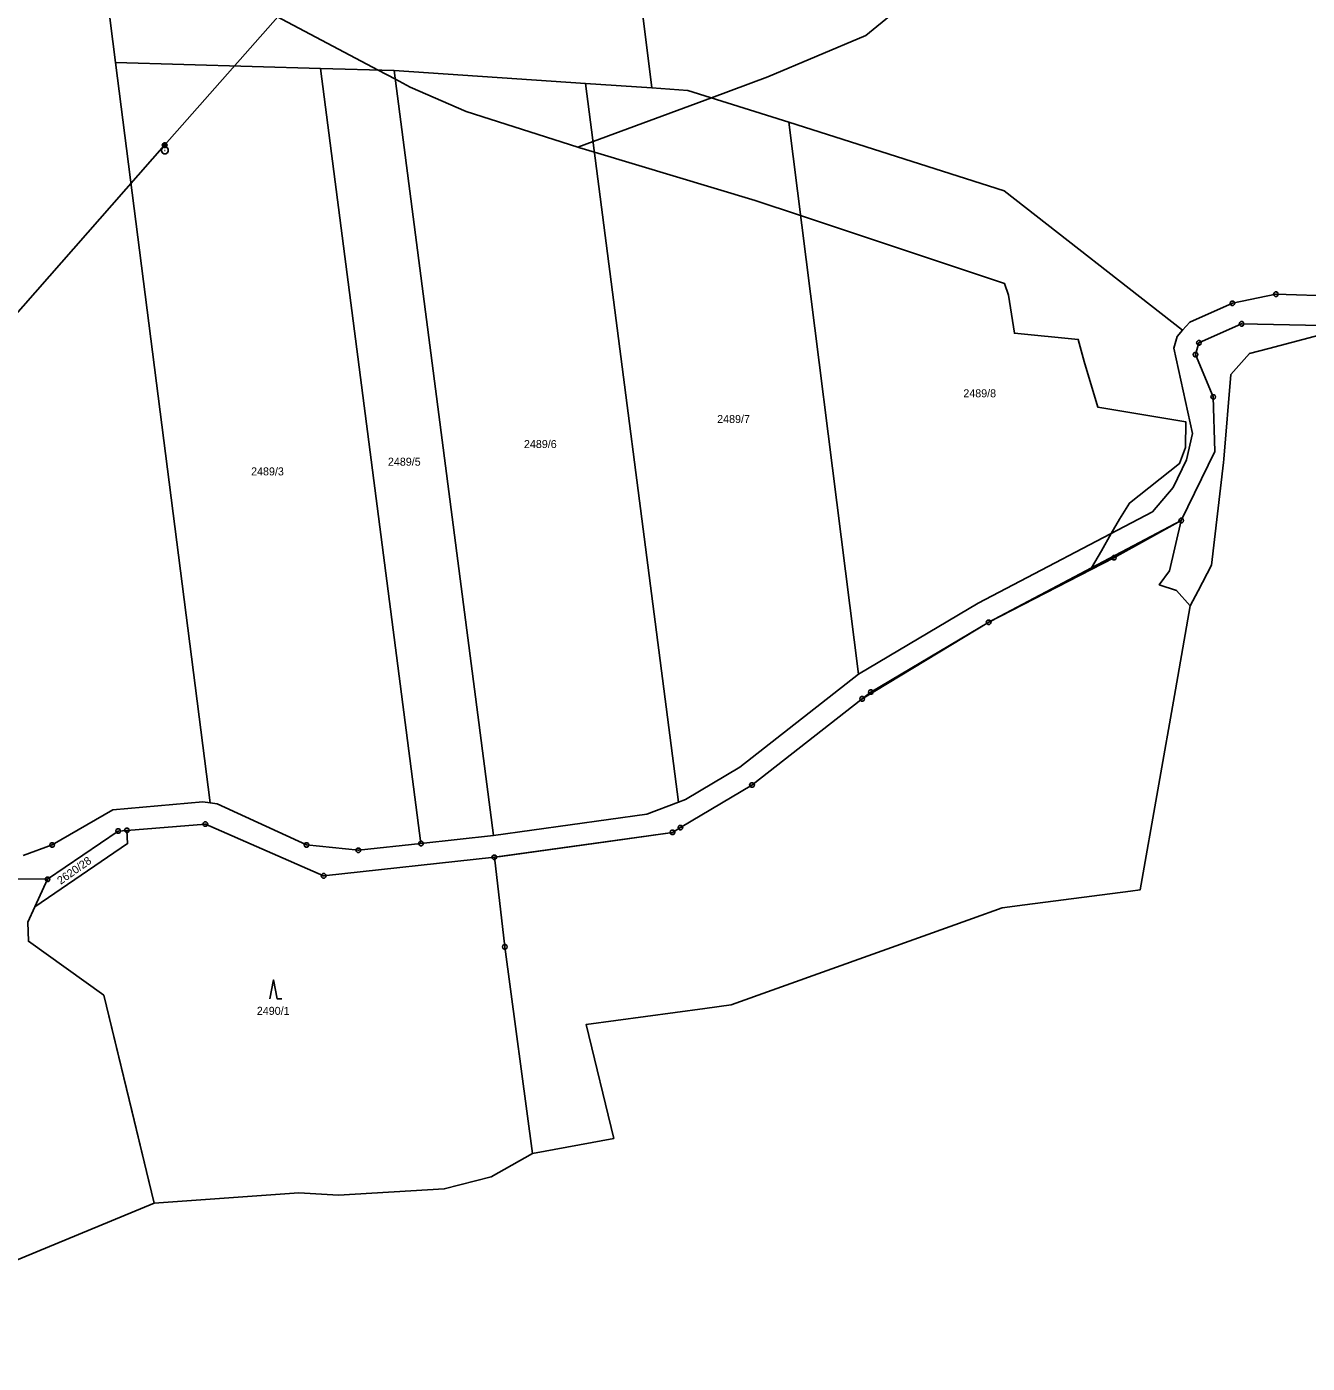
# Model space of a CAD drawing. Extents: x -760611 to -758411, y -1176479 to -1174807.
# Drawn here: x -759249.4 to -758977.4, y -1175576.9 to -1175293 of the extents above; entities that cross this region are included whole.
import ezdxf

# ---------------------------------------------------------------- set-up
doc = ezdxf.new("R2010")
doc.units = 0
for name, color, linetype in [('1', 7, 'Continuous'), ('11', 7, 'Continuous'), ('2', 7, 'Continuous'), ('3', 7, 'Continuous'), ('6', 7, 'Continuous'), ('8', 7, 'Continuous')]:
    doc.layers.add(name, color=color, linetype=linetype)

msp = doc.modelspace()

# ---------------------------------------------------------------- linework, layer by layer
at = {"layer": '1'}
for p, q in [((-759239.1, -1175233.43), (-759230.51, -1175300.62)), ((-759124.57, -1175242.76), (-759116.61, -1175306.03)), ((-759230.51, -1175300.62), (-759210.41, -1175457.91)), ((-759186.97, -1175301.88), (-759230.51, -1175300.62)), ((-759171.32, -1175302.34), (-759186.97, -1175301.88)), ((-759186.97, -1175301.88), (-759165.64, -1175466.52)), ((-759171.32, -1175302.34), (-759150.26, -1175464.85)), ((-759130.69, -1175305.08), (-759171.32, -1175302.34)), ((-759130.69, -1175305.08), (-759116.61, -1175306.03)), ((-759110.92, -1175457.7), (-759130.69, -1175305.08)), ((-759116.61, -1175306.03), (-759108.97, -1175306.54)), ((-759108.97, -1175306.54), (-759087.54, -1175313.33)), ((-759041.78, -1175327.91), (-759087.54, -1175313.33)), ((-759087.54, -1175313.33), (-759072.7, -1175430.56)), ((-759003.87, -1175357.51), (-759041.78, -1175327.91)), ((-758993.3, -1175351.77), (-759002.36, -1175355.79)), ((-758984.06, -1175349.84), (-758993.3, -1175351.77)), ((-758969.35, -1175350.34), (-758984.06, -1175349.84)), ((-759005.01, -1175358.82), (-759003.87, -1175357.51)), ((-759003.87, -1175357.51), (-759002.36, -1175355.79)), ((-759000.41, -1175360.18), (-758991.35, -1175356.15)), ((-758991.35, -1175356.15), (-758967.69, -1175356.63)), ((-759005.01, -1175358.82), (-759005.75, -1175361.32)), ((-759001.15, -1175362.68), (-759000.41, -1175360.18)), ((-759005.75, -1175361.32), (-759001.76, -1175379.4)), ((-758997.36, -1175371.67), (-759001.15, -1175362.68)), ((-758997.06, -1175383.23), (-758997.36, -1175371.67)), ((-759001.76, -1175379.4), (-759003.02, -1175385)), ((-759004.16, -1175397.91), (-758997.06, -1175383.23)), ((-759003.02, -1175385), (-759005.87, -1175390.89)), ((-759005.87, -1175390.89), (-759010.3, -1175396.05)), ((-759010.3, -1175396.05), (-759047.29, -1175415.5)), ((-759018.46, -1175405.83), (-759004.16, -1175397.91)), ((-759045.06, -1175419.53), (-759018.46, -1175405.83)), ((-759047.29, -1175415.5), (-759072.7, -1175430.56)), ((-759070.1, -1175434.37), (-759045.06, -1175419.53)), ((-759097.94, -1175450.29), (-759072.7, -1175430.56)), ((-759071.93, -1175435.8), (-759095.34, -1175454.1)), ((-759070.1, -1175434.37), (-759071.93, -1175435.8)), ((-759097.94, -1175450.29), (-759109.43, -1175457.14)), ((-759095.34, -1175454.1), (-759110.54, -1175463.15)), ((-759231.12, -1175459.35), (-759243.97, -1175466.82)), ((-759211.95, -1175457.67), (-759231.12, -1175459.35)), ((-759211.95, -1175457.67), (-759210.41, -1175457.91)), ((-759210.41, -1175457.91), (-759208.95, -1175458.12)), ((-759189.96, -1175466.83), (-759208.95, -1175458.12)), ((-759117.67, -1175460.27), (-759110.92, -1175457.7)), ((-759110.92, -1175457.7), (-759109.43, -1175457.14)), ((-759211.43, -1175462.39), (-759228.09, -1175463.72)), ((-759211.43, -1175462.39), (-759186.31, -1175473.39)), ((-759117.67, -1175460.27), (-759150.26, -1175464.85)), ((-759244.94, -1175474.11), (-759229.95, -1175463.87)), ((-759228.09, -1175463.72), (-759229.95, -1175463.87)), ((-759227.96, -1175466.53), (-759228.09, -1175463.72)), ((-759165.64, -1175466.52), (-759150.26, -1175464.85)), ((-759150.05, -1175469.45), (-759112.22, -1175464.15)), ((-759110.54, -1175463.15), (-759112.22, -1175464.15)), ((-759243.97, -1175466.82), (-759250.12, -1175469.05)), ((-759247.64, -1175479.98), (-759227.96, -1175466.53)), ((-759178.94, -1175467.96), (-759189.96, -1175466.83)), ((-759178.94, -1175467.96), (-759165.64, -1175466.52)), ((-759150.05, -1175469.45), (-759186.31, -1175473.39)), ((-759150.05, -1175469.45), (-759147.83, -1175488.47)), ((-759274.94, -1175473.79), (-759244.94, -1175474.11)), ((-759244.94, -1175474.11), (-759247.64, -1175479.98)), ((-759247.64, -1175479.98), (-759249.13, -1175483.21)), ((-759249.01, -1175487.28), (-759249.13, -1175483.21)), ((-759233.01, -1175498.74), (-759249.01, -1175487.28)), ((-759147.83, -1175488.47), (-759141.95, -1175532.33)), ((-759222.29, -1175542.91), (-759233.01, -1175498.74)), ((-759141.95, -1175532.33), (-759150.72, -1175537.34)), ((-759150.72, -1175537.34), (-759160.7, -1175539.89)), ((-759191.58, -1175540.71), (-759222.29, -1175542.91)), ((-759183.19, -1175541.19), (-759191.58, -1175540.71)), ((-759160.7, -1175539.89), (-759183.19, -1175541.19))]:
    msp.add_line(p, q, dxfattribs=at)
at = {"layer": '11'}
msp.add_line((-759002.27, -1175416.06), (-759005.42, -1175433.87), dxfattribs=at)
for points in [[(-758975.79, -1175178.19), (-758988.73, -1175187.68), (-758988.97, -1175187.85), (-758998.77, -1175199.65), (-759009, -1175216.53), (-759019.77, -1175236.09), (-759024.8, -1175245.22), (-759039.29, -1175265.46), (-759053.76, -1175280.62), (-759071.19, -1175294.92), (-759092, -1175303.7), (-759103.96, -1175308.13), (-759129.09, -1175317.42), (-759132.3, -1175318.61)], [(-759132.3, -1175318.61), (-759156.06, -1175311), (-759167.91, -1175305.86), (-759171.08, -1175304.18), (-759174.75, -1175302.24), (-759227.58, -1175274.25), (-759234.21, -1175271.67), (-759244.09, -1175267.82), (-759256.38, -1175263.95), (-759258.05, -1175258.44), (-759258.03, -1175252.52), (-759275.43, -1175254.97), (-759297.92, -1175261.21), (-759298.65, -1175261.35), (-759302.17, -1175262.03)], [(-759132.3, -1175318.61), (-759131.91, -1175318.74), (-759128.8, -1175319.67), (-759094.64, -1175329.93), (-759085.04, -1175333.12), (-759041.7, -1175347.54), (-759040.86, -1175350.08), (-759039.62, -1175358.13), (-759026.06, -1175359.46), (-759024.8, -1175364.13), (-759021.87, -1175373.87), (-759003.22, -1175376.93), (-759003.24, -1175382.43), (-759004.53, -1175385.81), (-759015.16, -1175394.22), (-759017.29, -1175397.59), (-759019.02, -1175400.64), (-759021.13, -1175404.34), (-759023.2, -1175407.97)], [(-758993.67, -1175366.93), (-758989.69, -1175362.44), (-758985.6, -1175361.36), (-758967.69, -1175356.63), (-758957.61, -1175355.92), (-758936.92, -1175355.2), (-758892.8, -1175353.02)], [(-758993.67, -1175366.93), (-758995.11, -1175384.9), (-758995.19, -1175385.57), (-758997.73, -1175407.38), (-759000.61, -1175412.88), (-759002.27, -1175416.06)], [(-759023.2, -1175407.97), (-759004.16, -1175397.91), (-759006.64, -1175408.62), (-759008.83, -1175411.55), (-759005.17, -1175412.8), (-759002.27, -1175416.06)], [(-759095.34, -1175454.1), (-759071.93, -1175435.8), (-759045.06, -1175419.53), (-759023.2, -1175407.97)], [(-759005.42, -1175433.87), (-759012.92, -1175476.36), (-759014.96, -1175476.62), (-759037.4, -1175479.54), (-759042.19, -1175480.16), (-759048.51, -1175482.42), (-759058.95, -1175486.17), (-759099.79, -1175500.8), (-759105.33, -1175501.55), (-759130.53, -1175504.94), (-759124.69, -1175529.2)], [(-759222.29, -1175542.91), (-759223.5, -1175537.94), (-759227, -1175523.49), (-759233.01, -1175498.74), (-759249.01, -1175487.28), (-759249.13, -1175483.21), (-759247.64, -1175479.98), (-759227.96, -1175466.53), (-759228.09, -1175463.72), (-759211.43, -1175462.39), (-759186.31, -1175473.39), (-759150.05, -1175469.45), (-759148.72, -1175469.31), (-759125.8, -1175466.07), (-759112.22, -1175464.15), (-759110.54, -1175463.15), (-759095.34, -1175454.1)], [(-759124.69, -1175529.2), (-759141.95, -1175532.33), (-759150.72, -1175537.34), (-759160.7, -1175539.89), (-759183.19, -1175541.19), (-759191.58, -1175540.71), (-759222.29, -1175542.91)], [(-759307.54, -1175578.1), (-759291.72, -1175571.57), (-759263.55, -1175559.94), (-759222.29, -1175542.91)]]:
    msp.add_lwpolyline(points, dxfattribs=at)
at = {"layer": '3'}
msp.add_lwpolyline([(-759197.72, -1175499.49), (-759196.97, -1175495.49), (-759196.22, -1175499.49), (-759195.22, -1175499.49)], dxfattribs=at)
at = {"layer": '6'}
for p, q in [((-759142.03, -1175229.64), (-759220.08, -1175318.2)), ((-759220.08, -1175318.2), (-759293.3, -1175401.37))]:
    msp.add_line(p, q, dxfattribs=at)
msp.add_lwpolyline([(-759220.23, -1175317.72), (-759219.92, -1175317.72), (-759219.67, -1175317.9), (-759219.57, -1175318.19), (-759219.67, -1175318.48), (-759219.92, -1175318.66), (-759220.23, -1175318.66), (-759220.48, -1175318.48), (-759220.58, -1175318.19), (-759220.48, -1175317.9), (-759220.23, -1175317.72), (-759220.2, -1175317.76), (-759219.96, -1175317.76), (-759219.8, -1175317.84), (-759220.36, -1175317.84), (-759220.44, -1175317.92), (-759219.72, -1175317.92), (-759219.72, -1175318), (-759220.44, -1175318), (-759220.48, -1175318.08), (-759219.68, -1175318.08), (-759219.64, -1175318.16), (-759220.52, -1175318.16), (-759220.52, -1175318.24), (-759219.64, -1175318.24), (-759219.67, -1175318.32), (-759220.48, -1175318.32), (-759220.47, -1175318.4), (-759219.66, -1175318.4), (-759219.71, -1175318.48), (-759220.43, -1175318.48), (-759220.35, -1175318.56), (-759219.79, -1175318.56), (-759219.9, -1175318.64), (-759220.24, -1175318.64)], dxfattribs=at)
at = {"layer": '8'}
for p, q in [((-759220.08, -1175319.29), (-759219.98, -1175319.29)), ((-758993.42, -1175351.77), (-758993.18, -1175351.77)), ((-758984.18, -1175349.84), (-758983.94, -1175349.84)), ((-758991.47, -1175356.15), (-758991.23, -1175356.15)), ((-759000.53, -1175360.18), (-759000.29, -1175360.18)), ((-759001.27, -1175362.68), (-759001.03, -1175362.68)), ((-758997.48, -1175371.67), (-758997.24, -1175371.67)), ((-759004.28, -1175397.91), (-759004.04, -1175397.91)), ((-759018.58, -1175405.83), (-759018.34, -1175405.83)), ((-759045.18, -1175419.53), (-759044.94, -1175419.53)), ((-759072.05, -1175435.8), (-759071.81, -1175435.8)), ((-759070.22, -1175434.37), (-759069.98, -1175434.37)), ((-759095.46, -1175454.1), (-759095.22, -1175454.1)), ((-759211.55, -1175462.39), (-759211.31, -1175462.39)), ((-759230.07, -1175463.87), (-759229.83, -1175463.87)), ((-759228.21, -1175463.72), (-759227.97, -1175463.72)), ((-759112.34, -1175464.15), (-759112.1, -1175464.15)), ((-759110.66, -1175463.15), (-759110.42, -1175463.15)), ((-759244.09, -1175466.82), (-759243.85, -1175466.82)), ((-759190.08, -1175466.83), (-759189.84, -1175466.83)), ((-759179.06, -1175467.96), (-759178.82, -1175467.96)), ((-759165.76, -1175466.52), (-759165.52, -1175466.52)), ((-759150.17, -1175469.45), (-759149.93, -1175469.45)), ((-759186.43, -1175473.39), (-759186.19, -1175473.39)), ((-759245.06, -1175474.11), (-759244.82, -1175474.11)), ((-759147.95, -1175488.47), (-759147.71, -1175488.47))]:
    msp.add_line(p, q, dxfattribs=at)
for points in [[(-759219.84, -1175318.57), (-759219.5, -1175318.76), (-759219.31, -1175319.1), (-759219.31, -1175319.49), (-759219.5, -1175319.83), (-759219.84, -1175320.02), (-759220.23, -1175320.02), (-759220.57, -1175319.83), (-759220.76, -1175319.49), (-759220.76, -1175319.1), (-759220.57, -1175318.76), (-759220.23, -1175318.57)], [(-758993.15, -1175351.29), (-758992.9, -1175351.47), (-758992.8, -1175351.76), (-758992.9, -1175352.05), (-758993.15, -1175352.23), (-758993.46, -1175352.23), (-758993.71, -1175352.05), (-758993.81, -1175351.76), (-758993.71, -1175351.47), (-758993.46, -1175351.29)], [(-758983.91, -1175349.36), (-758983.66, -1175349.54), (-758983.56, -1175349.83), (-758983.66, -1175350.12), (-758983.91, -1175350.3), (-758984.22, -1175350.3), (-758984.47, -1175350.12), (-758984.57, -1175349.83), (-758984.47, -1175349.54), (-758984.22, -1175349.36)], [(-758991.2, -1175355.67), (-758990.95, -1175355.85), (-758990.85, -1175356.14), (-758990.95, -1175356.43), (-758991.2, -1175356.61), (-758991.51, -1175356.61), (-758991.76, -1175356.43), (-758991.86, -1175356.14), (-758991.76, -1175355.85), (-758991.51, -1175355.67)], [(-759000.26, -1175359.7), (-759000.01, -1175359.88), (-758999.91, -1175360.17), (-759000.01, -1175360.46), (-759000.26, -1175360.64), (-759000.57, -1175360.64), (-759000.82, -1175360.46), (-759000.92, -1175360.17), (-759000.82, -1175359.88), (-759000.57, -1175359.7)], [(-759001, -1175362.2), (-759000.75, -1175362.38), (-759000.65, -1175362.67), (-759000.75, -1175362.96), (-759001, -1175363.14), (-759001.31, -1175363.14), (-759001.56, -1175362.96), (-759001.66, -1175362.67), (-759001.56, -1175362.38), (-759001.31, -1175362.2)], [(-758997.21, -1175371.19), (-758996.96, -1175371.37), (-758996.86, -1175371.66), (-758996.96, -1175371.95), (-758997.21, -1175372.13), (-758997.52, -1175372.13), (-758997.77, -1175371.95), (-758997.87, -1175371.66), (-758997.77, -1175371.37), (-758997.52, -1175371.19)], [(-759004.01, -1175397.43), (-759003.76, -1175397.61), (-759003.66, -1175397.9), (-759003.76, -1175398.19), (-759004.01, -1175398.37), (-759004.32, -1175398.37), (-759004.57, -1175398.19), (-759004.67, -1175397.9), (-759004.57, -1175397.61), (-759004.32, -1175397.43)], [(-759018.31, -1175405.35), (-759018.06, -1175405.53), (-759017.96, -1175405.82), (-759018.06, -1175406.11), (-759018.31, -1175406.29), (-759018.62, -1175406.29), (-759018.87, -1175406.11), (-759018.97, -1175405.82), (-759018.87, -1175405.53), (-759018.62, -1175405.35)], [(-759044.91, -1175419.05), (-759044.66, -1175419.23), (-759044.56, -1175419.52), (-759044.66, -1175419.81), (-759044.91, -1175419.99), (-759045.22, -1175419.99), (-759045.47, -1175419.81), (-759045.57, -1175419.52), (-759045.47, -1175419.23), (-759045.22, -1175419.05)], [(-759069.95, -1175433.89), (-759069.7, -1175434.07), (-759069.6, -1175434.36), (-759069.7, -1175434.65), (-759069.95, -1175434.83), (-759070.26, -1175434.83), (-759070.51, -1175434.65), (-759070.61, -1175434.36), (-759070.51, -1175434.07), (-759070.26, -1175433.89)], [(-759071.78, -1175435.32), (-759071.53, -1175435.5), (-759071.43, -1175435.79), (-759071.53, -1175436.08), (-759071.78, -1175436.26), (-759072.09, -1175436.26), (-759072.34, -1175436.08), (-759072.44, -1175435.79), (-759072.34, -1175435.5), (-759072.09, -1175435.32)], [(-759095.19, -1175453.62), (-759094.94, -1175453.8), (-759094.84, -1175454.09), (-759094.94, -1175454.38), (-759095.19, -1175454.56), (-759095.5, -1175454.56), (-759095.75, -1175454.38), (-759095.85, -1175454.09), (-759095.75, -1175453.8), (-759095.5, -1175453.62)], [(-759211.28, -1175461.91), (-759211.03, -1175462.09), (-759210.93, -1175462.38), (-759211.03, -1175462.67), (-759211.28, -1175462.85), (-759211.59, -1175462.85), (-759211.84, -1175462.67), (-759211.94, -1175462.38), (-759211.84, -1175462.09), (-759211.59, -1175461.91)], [(-759110.39, -1175462.67), (-759110.14, -1175462.85), (-759110.04, -1175463.14), (-759110.14, -1175463.43), (-759110.39, -1175463.61), (-759110.7, -1175463.61), (-759110.95, -1175463.43), (-759111.05, -1175463.14), (-759110.95, -1175462.85), (-759110.7, -1175462.67)], [(-759229.8, -1175463.39), (-759229.55, -1175463.57), (-759229.45, -1175463.86), (-759229.55, -1175464.15), (-759229.8, -1175464.33), (-759230.11, -1175464.33), (-759230.36, -1175464.15), (-759230.46, -1175463.86), (-759230.36, -1175463.57), (-759230.11, -1175463.39)], [(-759227.94, -1175463.24), (-759227.69, -1175463.42), (-759227.59, -1175463.71), (-759227.69, -1175464), (-759227.94, -1175464.18), (-759228.25, -1175464.18), (-759228.5, -1175464), (-759228.6, -1175463.71), (-759228.5, -1175463.42), (-759228.25, -1175463.24)], [(-759112.07, -1175463.67), (-759111.82, -1175463.85), (-759111.72, -1175464.14), (-759111.82, -1175464.43), (-759112.07, -1175464.61), (-759112.38, -1175464.61), (-759112.63, -1175464.43), (-759112.73, -1175464.14), (-759112.63, -1175463.85), (-759112.38, -1175463.67)], [(-759243.82, -1175466.34), (-759243.57, -1175466.52), (-759243.47, -1175466.81), (-759243.57, -1175467.1), (-759243.82, -1175467.28), (-759244.13, -1175467.28), (-759244.38, -1175467.1), (-759244.48, -1175466.81), (-759244.38, -1175466.52), (-759244.13, -1175466.34)], [(-759189.81, -1175466.35), (-759189.56, -1175466.53), (-759189.46, -1175466.82), (-759189.56, -1175467.11), (-759189.81, -1175467.29), (-759190.12, -1175467.29), (-759190.37, -1175467.11), (-759190.47, -1175466.82), (-759190.37, -1175466.53), (-759190.12, -1175466.35)], [(-759178.79, -1175467.48), (-759178.54, -1175467.66), (-759178.44, -1175467.95), (-759178.54, -1175468.24), (-759178.79, -1175468.42), (-759179.1, -1175468.42), (-759179.35, -1175468.24), (-759179.45, -1175467.95), (-759179.35, -1175467.66), (-759179.1, -1175467.48)], [(-759165.49, -1175466.04), (-759165.24, -1175466.22), (-759165.14, -1175466.51), (-759165.24, -1175466.8), (-759165.49, -1175466.98), (-759165.8, -1175466.98), (-759166.05, -1175466.8), (-759166.15, -1175466.51), (-759166.05, -1175466.22), (-759165.8, -1175466.04)], [(-759149.9, -1175468.97), (-759149.65, -1175469.15), (-759149.55, -1175469.44), (-759149.65, -1175469.73), (-759149.9, -1175469.91), (-759150.21, -1175469.91), (-759150.46, -1175469.73), (-759150.56, -1175469.44), (-759150.46, -1175469.15), (-759150.21, -1175468.97)], [(-759244.79, -1175473.63), (-759244.54, -1175473.81), (-759244.44, -1175474.1), (-759244.54, -1175474.39), (-759244.79, -1175474.57), (-759245.1, -1175474.57), (-759245.35, -1175474.39), (-759245.45, -1175474.1), (-759245.35, -1175473.81), (-759245.1, -1175473.63)], [(-759186.16, -1175472.91), (-759185.91, -1175473.09), (-759185.81, -1175473.38), (-759185.91, -1175473.67), (-759186.16, -1175473.85), (-759186.47, -1175473.85), (-759186.72, -1175473.67), (-759186.82, -1175473.38), (-759186.72, -1175473.09), (-759186.47, -1175472.91)], [(-759147.68, -1175487.99), (-759147.43, -1175488.17), (-759147.33, -1175488.46), (-759147.43, -1175488.75), (-759147.68, -1175488.93), (-759147.99, -1175488.93), (-759148.24, -1175488.75), (-759148.34, -1175488.46), (-759148.24, -1175488.17), (-759147.99, -1175487.99)]]:
    msp.add_lwpolyline(points, close=True, dxfattribs=at)

# ---------------------------------------------------------------- texts
at = {"layer": '2'}
for s, p in [('2489/8', (-759050.45, -1175371.74)), ('2489/7', (-759102.73, -1175377.2)), ('2489/6', (-759143.77, -1175382.52)), ('2489/5', (-759172.66, -1175386.27)), ('2489/3', (-759201.72, -1175388.33)), ('2490/1', (-759200.5, -1175502.91))]:
    msp.add_text(s, height=1.7, dxfattribs=at).set_placement(p)
msp.add_text('2620/28', height=1.7, rotation=35.3515, dxfattribs=at).set_placement((-759242.15, -1175475.3))

doc.saveas('drawing.dxf')
